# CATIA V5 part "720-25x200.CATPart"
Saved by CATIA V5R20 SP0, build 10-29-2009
Part number: 720-25x200
Definition: NONE
Nomenclature: 720-25x200
Source: Unknown
Description: 720-25x200
Bounding box of the stored display mesh (mm): x 0 to 200, y -12.5 to 12.5, z -12.5 to 12.5
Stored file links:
  C:\Users\Utente\Desktop\IO LAVORO\3D X SITO CF\X SITO\720\720-25x200.CATPart
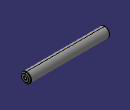
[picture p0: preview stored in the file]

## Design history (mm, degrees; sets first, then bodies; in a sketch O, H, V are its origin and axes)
Body1 "720-25x200" (main body)
  Solid1: solid without history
